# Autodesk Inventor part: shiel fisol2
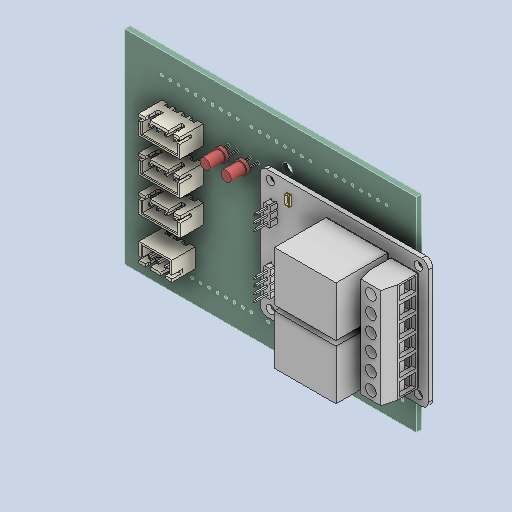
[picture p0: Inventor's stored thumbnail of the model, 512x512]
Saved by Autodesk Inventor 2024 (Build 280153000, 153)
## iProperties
Created: 2025-05
Part Number: shiel fisol2
Material: Generic
Description: KiCad electronic assembly
Document SubType Name: Modeling
Designer: MRIF'AN
Authority: Unknown
Density: 1 g/cm^3
Appearance: Default
Company: Kicad
Title: shiel fisol2.step
Author: Pcbnew
Sending System: KiCad to STEP converter
Preprocessor: Open CASCADE STEP processor 7.8
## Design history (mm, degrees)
feature "1:1"
feature "1:2"
feature "1:3"
feature "1:4"
feature "1:5"
feature "1:6"
feature "1:7"
feature "1:8"
feature "1:9"
feature "1:10"
feature "1:11"
feature "1:12"
feature "1:13"
feature "1:14"
feature "1:15"
feature "1:16"
feature "1:17"
feature "1:18"
feature "1:19"
feature "1:20"
feature "1:21"
feature "1:22"
feature "1:23"
feature "1:24"
feature "3:1"
feature "5:1"
feature "5:2"
feature "8:1"
feature "5:3"
feature "3:2"
feature "12:1"
feature "12:2"
feature "15:1"
body "Solid1"
body "Solid2"
body "Solid3"
body "Solid4"
body "Solid5"
body "Solid6"
body "Solid7"
body "Solid8"
body "Solid9"
body "Solid10"
body "Solid11"
body "Solid12"
body "Solid13"
body "Solid14"
body "Solid15"
body "Solid16"
body "Solid17"
body "Solid18"
body "Solid19"
body "Solid20"
body "Solid21"
body "Solid22"
body "Solid23"
body "Solid24"
body "Solid25"
body "Solid26"
body "Solid27"
body "Solid28"
body "Solid29"
body "Solid30"
body "Solid31"
body "Solid32"
body "Solid33"
